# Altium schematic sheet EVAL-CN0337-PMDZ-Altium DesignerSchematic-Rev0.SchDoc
size A4
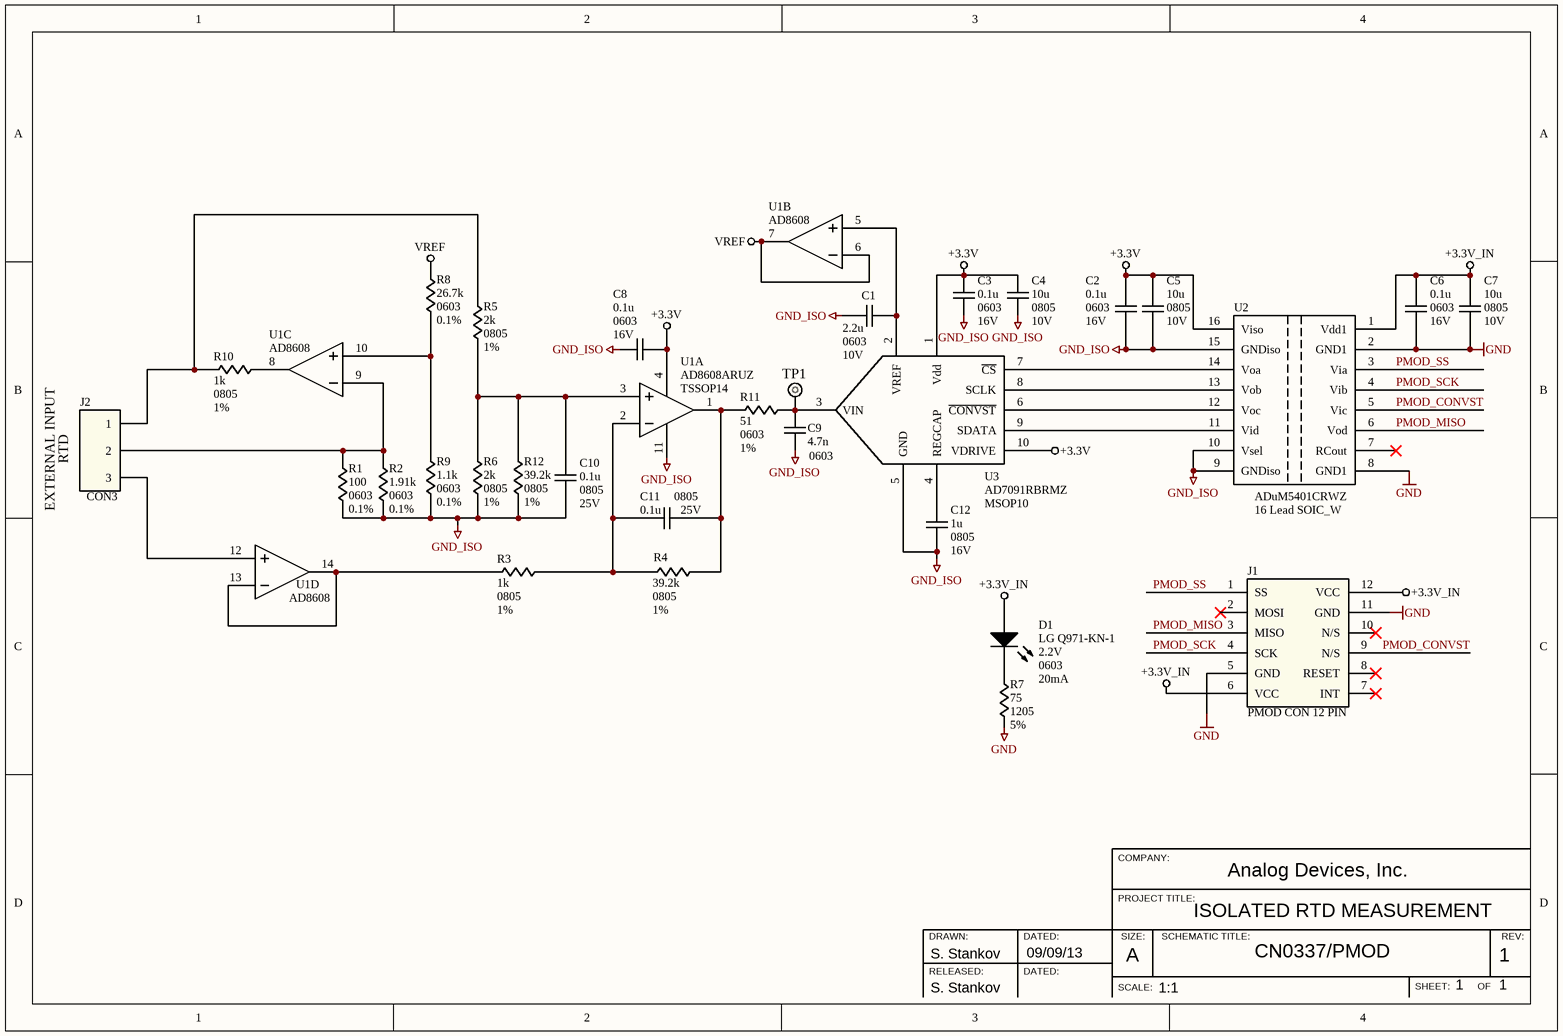
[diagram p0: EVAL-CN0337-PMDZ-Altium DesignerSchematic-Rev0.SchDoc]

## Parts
C1  value 2.2u  Footprint: 0603  Voltage: 10V  [0805 AD]
C2  value 0.1u  Footprint: 0603  Voltage: 16V  [0603 AD]
C3  value 0.1u  Footprint: 0603  Voltage: 16V  [0603 AD]
C4  value 10u  Footprint: 0805  Voltage: 10V  [0805 AD]
C5  value 10u  Footprint: 0805  Voltage: 10V  [0805 AD]  (hidden comment: Cap)
C6  value 0.1u  Footprint: 0603  Voltage: 16V  [0603 AD]
C7  value 10u  Footprint: 0805  Voltage: 10V  [0805 AD]  (hidden comment: Cap)
C8  value 0.1u  Footprint: 0603  Voltage: 16V  [0603 AD]
C9  value 4.7n  Footprint: 0603  [0603 AD]
C10  value 0.1u  Footprint: 0805  Voltage: 25V  [0805 AD]
C11  value 0.1u  Footprint: 0805  Voltage: 25V  [0805 AD]
C12  value 1u  Footprint: 0805  Voltage: 16V  [0805 AD]
D1  value LG Q971-KN-1  Drop Voltage: 2.2V  Footprint: 0603  Current: 20mA  [0603 Diode]  (hidden comment: LED3)
J1  PMOD CON 12 Pin  [PMOD 12 Pin]
J2  CON3  [Phoenix_3pin_pitch2_25]
R1  value 100  Footrprint: 0603  Tolerance: 0.1%  [0603 AD]  (hidden comment: RESISTOR)
R2  value 1.91k  Footrprint: 0603  Tolerance: 0.1%  [0603 AD]  (hidden comment: RESISTOR)
R3  value 1k  Footrprint: 0805  Tolerance: 1%  [0805 AD]  (hidden comment: RESISTOR)
R4  value 39.2k  Footrprint: 0805  Tolerance: 1%  [0805 AD]  (hidden comment: RESISTOR)
R5  value 2k  Footrprint: 0805  Tolerance: 1%  [0805 AD]  (hidden comment: RESISTOR)
R6  value 2k  Footrprint: 0805  Tolerance: 1%  [0805 AD]  (hidden comment: RESISTOR)
R7  value 75  Footrprint: 1205  Tolerance: 5%  [1206 AD]  (hidden comment: RESISTOR)
R8  value 26.7k  Footrprint: 0603  Tolerance: 0.1%  [0603 AD]  (hidden comment: RESISTOR)
R9  value 1.1k  Footrprint: 0603  Tolerance: 0.1%  [0603 AD]  (hidden comment: RESISTOR)
R10  value 1k  Footrprint: 0805  Tolerance: 1%  [0805 AD]  (hidden comment: RESISTOR)
R11  value 51  Footrprint: 0603  Tolerance: 1%  [0603 AD]  (hidden comment: RESISTOR)
R12  value 39.2k  Footrprint: 0805  Tolerance: 1%  [0805 AD]  (hidden comment: RESISTOR)
TP1  TestPoint  [TestPoint]  (value not drawn)
U1  value AD8608ARUZ  [TSSOP14]  (hidden comment: AD8608)  (parts A,B,C,D of 4)
U2  value ADuM5401CRWZ  Footprint: 16 Lead SOIC_W  [SOICW_16]  (hidden comment: ADuM5401)
U3  value AD7091RBRMZ  [MSOP10]  (hidden comment: AD7091R)

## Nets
+3.3V: C2.2 C3.1 C4.1 C5.2 C8.2 U1.4(V+) U2.16(Viso) U3.1(Vdd) U3.10(VDRIVE)
+3.3V_IN: C6.2 C7.2 D1.A J1.6(VCC) J1.12(VCC) U2.1(Vdd1)
GND: C6.1 C7.1 J1.5(GND) J1.11(GND) R7.1 U2.2(GND1) U2.8(GND1)
GND_ISO: C1.2 C2.1 C3.2 C4.2 C5.1 C8.1 C9.1 C10.1 C12.2 R1.1 R2.1 R6.1 R9.1 R12.1 U1.11(V-) U2.9(GNDiso) U2.10(Vsel) U2.15(GNDiso) U3.5(GND)
VREF: R8.2 U1.6(-INB) U1.7(OUTB)
PMOD_CONVST: J1.9(N/S) U2.5(Vic)
PMOD_MISO: J1.3(MISO) U2.6(Vod)
PMOD_SCK: J1.4(SCK) U2.4(Vib)
PMOD_SS: J1.1(SS) U2.3(Via)
NetC1_1: C1.1 U1.5(+INB) U3.2(VREF)
NetC9_2: C9.2 R11.1 TP1.1 U3.3(VIN)
NetC10_2: C10.2 R5.1 R6.2 R12.2 U1.3(+INA)
NetC11_1: C11.1 R4.1 R11.2 U1.1(OUTA)
NetC11_2: C11.2 R3.1 R4.2 U1.2(-INA)
NetC12_1: C12.1 U3.4(REGCAP)
NetD1_K: D1.K R7.2
NetJ2_1: J2.1 R5.2 R10.2
NetJ2_2: J2.2 R1.2 R2.2 U1.9(-INC)
NetJ2_3: J2.3 U1.12(+IND)
NetR3_2: R3.2 U1.13(-IND) U1.14(OUTD)
NetR8_1: R8.1 R9.2 U1.10(+INC)
NetR10_1: R10.1 U1.8(OUTC)
NetU2_11: U2.11(Vid) U3.9(SDATA)
NetU2_12: U2.12(Voc) U3.6(~{CONVST})
NetU2_13: U2.13(Vob) U3.8(SCLK)
NetU2_14: U2.14(Voa) U3.7(~{CS})

Not connected (* = marked no-connect by the designer): J1 2(MOSI)* 7(INT)* 8(RESET)* 10(N/S)*; U2 7(RCout)*

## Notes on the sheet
- EXTERNAL INPUT
- (near J2) RTD
- COMPANY:
- PROJECT TITLE:
- ISOLATED RTD MEASUREMENT
- Analog Devices, Inc.
- DRAWN:
- RELEASED:
- S. Stankov
- DATED:
- 09/09/13
- SCALE:
- SIZE:
- A
- SCHEMATIC TITLE:
- CN0337/PMOD
- SHEET:           OF
- 1
- REV:
- 1:1

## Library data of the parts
C1 = Cap: Capacitor; Part Number: 7000305
C2 C3 C6 C8 = Cap: Capacitor; Part Number: 7000814
C4 C5 C7 = Cap: Capacitor; Part Number: 7000461
C9 = Cap: Capacitor; Part Number: 7000387; Voltage: 50V
C10 C11 = Cap: Capacitor; Part Number: 7000758
C12 = Cap: Capacitor; Part Number: 7000143
D1 = LED3: LED; Part Number: LG Q971-KN-1-0-20-R18
J1 = PMOD CON 12 Pin: PMOD CONNECTOR 12 PIN
J2 = CON3: Connector 2 Pin
R2 = RESISTOR: Part Number: 7000698
R3 R10 = RESISTOR: Part Number: 7000822
R5 R6 = RESISTOR: Part Number: 7001433
R7 = RESISTOR: Part Number: 7000144
R9 = RESISTOR: Part Number: 7000843
R11 = RESISTOR: Part Number: 7001199
U1 = AD8608: Operational Amplifier; Part Number: 30-025016-01
U2 = ADuM5401: Integrated Circuit; Part Number: 30-025173-01
U3 = AD7091R: ADC; Part Number: 30-026273-01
